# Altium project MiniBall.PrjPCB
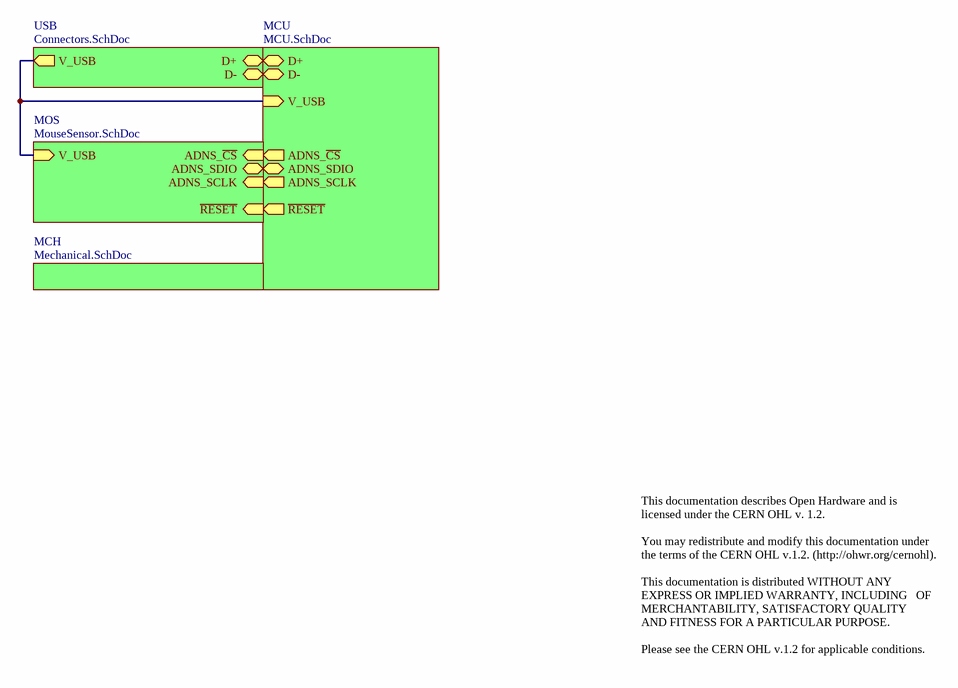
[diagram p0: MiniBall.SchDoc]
5 sheets, 44 parts. Net scope: hierarchical (ports join the sheet entries above them; power ports are global).
Board file: MiniBall.PcbDoc
Sheets:
  MiniBall.SchDoc
    USB = Connectors.SchDoc
    MCU = MCU.SchDoc
    MCH = Mechanical.SchDoc
    MOS = MouseSensor.SchDoc

## Sheet MiniBall.SchDoc
size Letter; CompanyName: Ploopy Corporation; Organization: Ploopy Corporation; Address1: 137-1140 Burnhamthorpe Road W; Address2: Mississauga; Address3: Ontario; Address4: Canada L5C 0A3; DocumentNumber: 1; Revision: R1.001; SheetNumber: 1; SheetTotal: 5

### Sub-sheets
MCH = Mechanical.SchDoc: no entries
MCU = MCU.SchDoc: D+ (bidir), D- (bidir), V_USB (in), ~{RESET} (out), ADNS_SDIO (bidir), ADNS_~{CS} (out), ADNS_SCLK (out)
MOS = MouseSensor.SchDoc: ~{RESET} (in), V_USB (in), ADNS_~{CS} (in), ADNS_SDIO (bidir), ADNS_SCLK (in)
USB = Connectors.SchDoc: D+ (bidir), V_USB (out), D- (bidir)

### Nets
~{RESET}: sheet MCU/~{RESET}, sheet MOS/~{RESET}
V_USB: sheet USB/V_USB, sheet MCU/V_USB, sheet MOS/V_USB
NetR6_2: sheet USB/D-, sheet MCU/D-
NetR7_2: sheet USB/D+, sheet MCU/D+
NetU1_12: sheet MCU/ADNS_SCLK, sheet MOS/ADNS_SCLK
NetU1_28: sheet MCU/ADNS_~{CS}, sheet MOS/ADNS_~{CS}
NetU1_31: sheet MCU/ADNS_SDIO, sheet MOS/ADNS_SDIO

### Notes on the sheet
- This documentation describes Open Hardware and is licensed under the CERN OHL v. 1.2.
  You may redistribute and modify this documentation under the terms of the CERN OHL v.1.2. (http://ohwr.org/cernohl).
  This documentation is distributed WITHOUT ANY EXPRESS OR IMPLIED WARRANTY, INCLUDING   OF MERCHANTABILITY, SATISFACTORY QUALITY   AND FITNESS FOR A PARTICULAR PURPOSE.
  Please see the CERN OHL v.1.2 for applicable conditions.

## Sheet Connectors.SchDoc
size Letter; CompanyName: Ploopy Corporation; Organization: Ploopy Corporation; Address1: 137-1140 Burnhamthorpe Road W; Address2: Mississauga; Address3: Ontario; Address4: Canada L5C 0A3; DocumentNumber: 2; Revision: R1.001; SheetNumber: 2; SheetTotal: 5
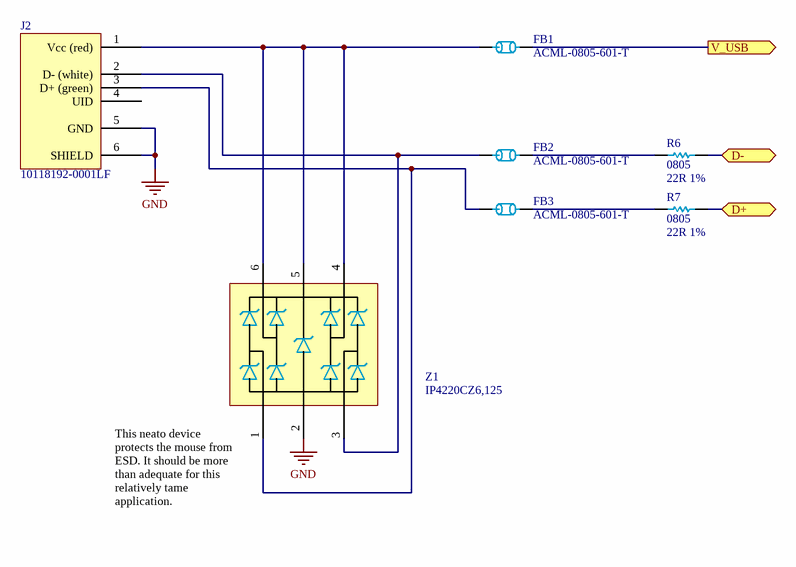
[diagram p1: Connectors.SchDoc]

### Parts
FB1  ACML-0805-601-T  [0805]
FB2  ACML-0805-601-T  [0805]
FB3  ACML-0805-601-T  [0805]
J2  10118192-0001LF  [10118192-0001LF]
R6  0805  value 22R 1%  [0805]
R7  0805  value 22R 1%  [0805]
Z1  IP4220CZ6,125  [PESD3V3S4UD - SOT95P275X110-6N]

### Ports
D+ (bidir), D- (bidir), V_USB (out)

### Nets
GND: J2.5(GND) J2.6(SHIELD) Z1.2
V_USB: FB1.2 ; port V_USB
NetFB1_1: FB1.1 J2.1(Vcc_(red)) Z1.4 Z1.5 Z1.6
NetFB2_1: FB2.1 J2.2(D-_(white)) Z1.3
NetFB2_2: FB2.2 R6.1
NetFB3_1: FB3.1 J2.3(D+_(green)) Z1.1
NetFB3_2: FB3.2 R7.1
NetR6_2: R6.2 ; port D-
NetR7_2: R7.2 ; port D+

Not connected (* = marked no-connect by the designer): J2 4(UID)

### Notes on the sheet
- (near Z1) This neato device protects the mouse from ESD. It should be more than adequate for this relatively tame application.

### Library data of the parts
FB1-FB3 = ACML-0805-601-T: FERRITE BEAD 600 OHM 0805 1LN; Value: Ferrite Bead 600R
J2 = 10118192-0001LF: CONN RCPT USB2.0 MICRO B SMD R/A
R6 R7 = Res 22R 1% 0805: Chip resistor
Z1 = IP4220CZ6,125: TVS DIODE 5.5V 6TSOP (Low capacitance, USB)

## Sheet MCU.SchDoc
size Legal; CompanyName: Ploopy Corporation; Organization: Ploopy Corporation; Address1: 137-1140 Burnhamthorpe Road W; Address2: Mississauga; Address3: Ontario; Address4: Canada L5C 0A3; DocumentNumber: 3; Revision: R1.001; SheetNumber: 3; SheetTotal: 5
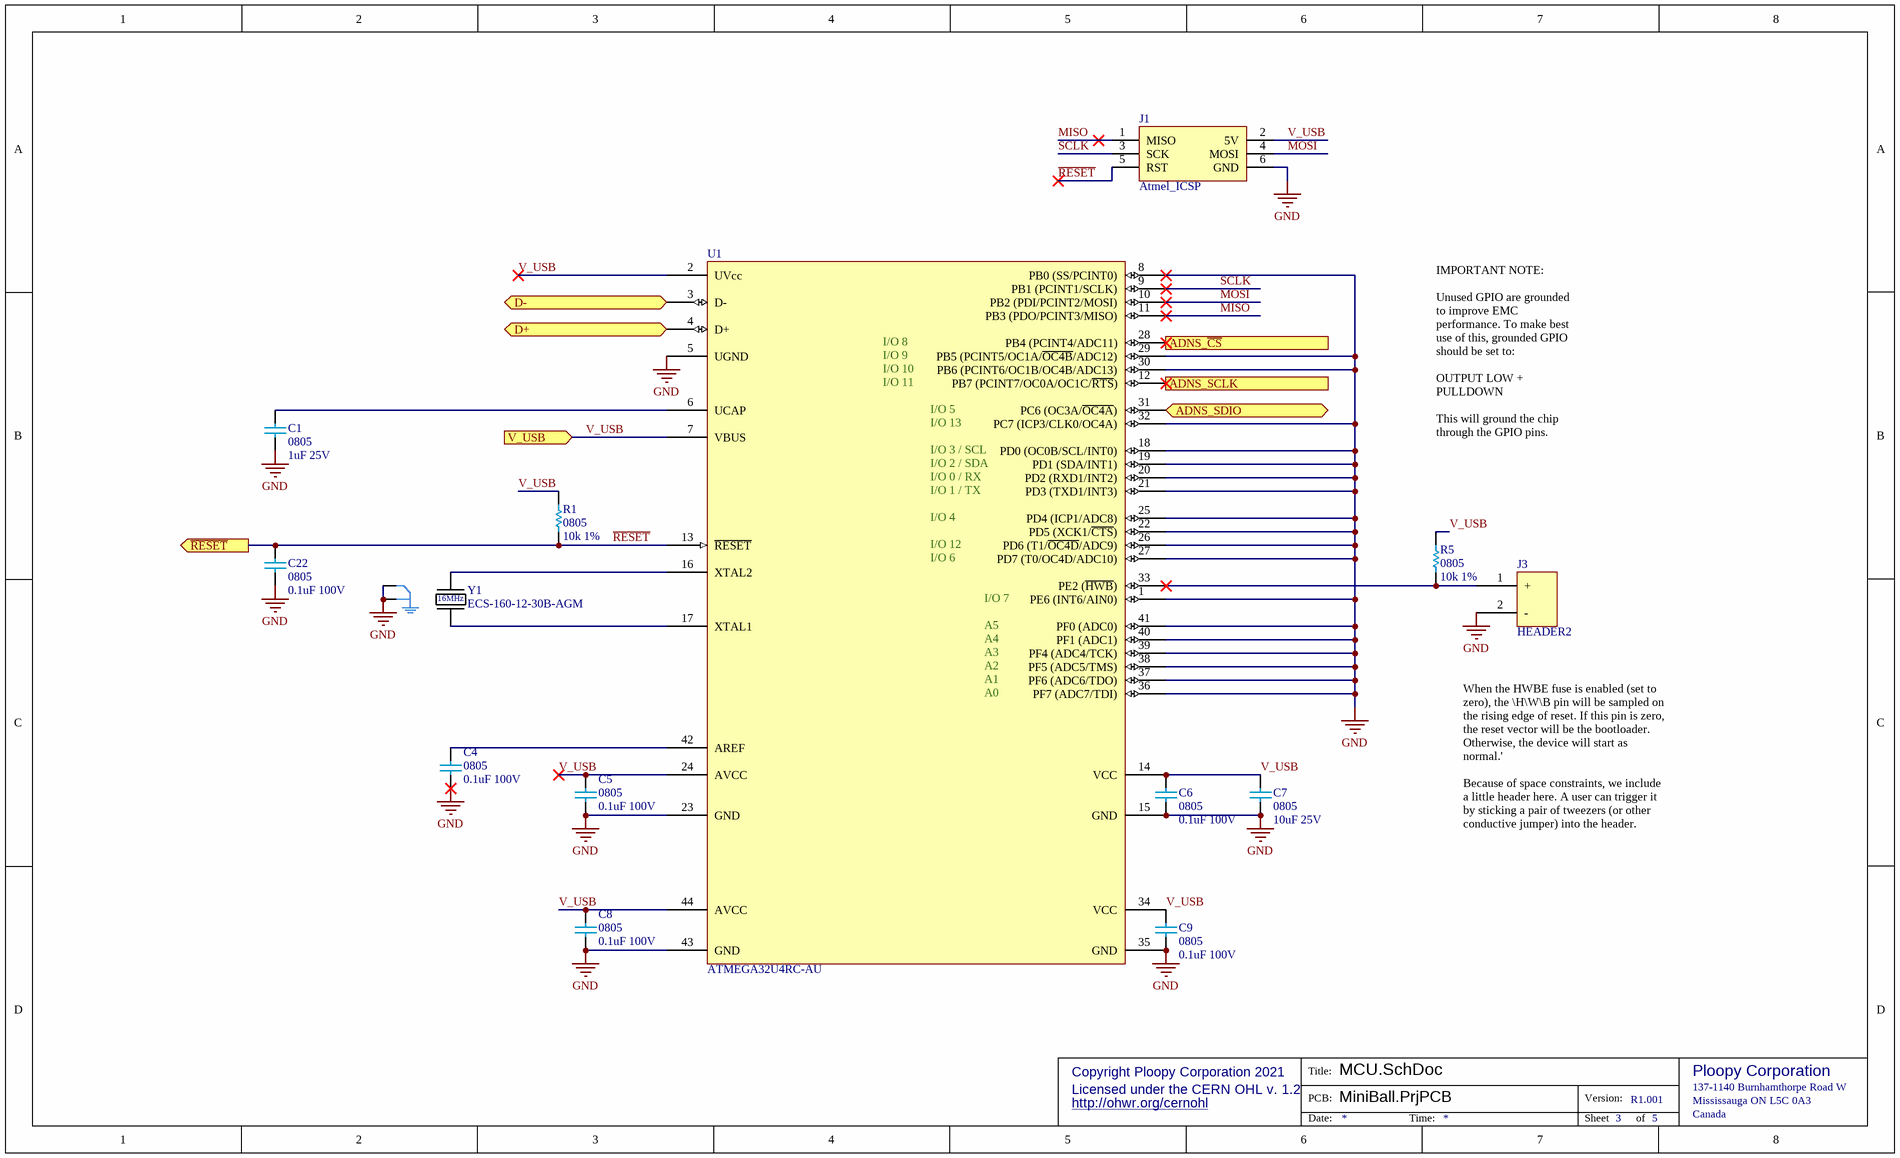
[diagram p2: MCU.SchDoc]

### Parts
C1  0805  value 1uF 25V  [0805 - TALL]
C4  0805  value 0.1uF 100V  [0805 - TALL]
C5  0805  value 0.1uF 100V  [0805 - TALL]
C6  0805  value 0.1uF 100V  [0805 - TALL]
C7  0805  value 10uF 25V  [0805 - TALL]
C8  0805  value 0.1uF 100V  [0805 - TALL]
C9  0805  value 0.1uF 100V  [0805 - TALL]
C22  0805  value 0.1uF 100V  [0805 - TALL]
J1  Atmel_ICSP  [6x2]
J3  HEADER2  [2x1]
R1  0805  value 10k 1%  [0805]
R5  0805  value 10k 1%  [0805]
U1  ATMEGA32U4RC-AU  [ATmega32U4 - TQFP80P1200X1200X120-44N]
Y1  ECS-160-12-30B-AGM  [LFXTAL055663BULK]

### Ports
ADNS_SCLK (out), ADNS_SDIO (bidir), ADNS_~{CS} (out), D+ (bidir), D- (bidir), V_USB (in), ~{RESET} (out)

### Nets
GND: C1.1 C4.1 C5.1 C6.1 C7.1 C8.1 C9.1 C22.1 J1.6(GND) J3.2(-) U1.1(PE6_(INT6/AIN0)) U1.5(UGND) U1.8(PB0_(SS/PCINT0)) U1.15(GND) U1.18(PD0_(OC0B/SCL/INT0)) U1.19(PD1_(SDA/INT1)) U1.20(PD2_(RXD1/INT2)) U1.21(PD3_(TXD1/INT3)) U1.22(PD5_(XCK1/~{CTS})) U1.23(GND) U1.25(PD4_(ICP1/ADC8)) U1.26(PD6_(T1/~{OC4D}/ADC9)) U1.27(PD7_(T0/OC4D/ADC10)) U1.29(PB5_(PCINT5/OC1A/~{OC4B}/ADC12)) U1.30(PB6_(PCINT6/OC1B/OC4B/ADC13)) U1.32(PC7_(ICP3/CLK0/OC4A)) U1.35(GND) U1.36(PF7_(ADC7/TDI)) U1.37(PF6_(ADC6/TDO)) U1.38(PF5_(ADC5/TMS)) U1.39(PF4_(ADC4/TCK)) U1.40(PF1_(ADC1)) U1.41(PF0_(ADC0)) U1.43(GND) Y1.2 Y1.4
MISO: J1.1(MISO) U1.11(PB3_(PDO/PCINT3/MISO))
MOSI: J1.4(MOSI) U1.10(PB2_(PDI/PCINT2/MOSI))
~{RESET}: C22.2 J1.5(RST) R1.1 U1.13(~{RESET}) ; port ~{RESET}
SCLK: J1.3(SCK) U1.9(PB1_(PCINT1/SCLK))
V_USB: C5.2 C6.2 C7.2 C8.2 C9.2 J1.2(5V) R1.2 R5.2 U1.2(UVcc) U1.7(VBUS) U1.14(VCC) U1.24(AVCC) U1.34(VCC) U1.44(AVCC) ; port V_USB
NetC1_2: C1.2 U1.6(UCAP)
NetC4_2: C4.2 U1.42(AREF)
NetJ3_1: J3.1(+) R5.1 U1.33(PE2_(~{HWB}))
NetR6_2: U1.3(D-) ; port D-
NetR7_2: U1.4(D+) ; port D+
NetU1_12: U1.12(PB7_(PCINT7/OC0A/OC1C/~{RTS})) ; port ADNS_SCLK
NetU1_16: U1.16(XTAL2) Y1.1
NetU1_17: U1.17(XTAL1) Y1.3
NetU1_28: U1.28(PB4_(PCINT4/ADC11)) ; port ADNS_~{CS}
NetU1_31: U1.31(PC6_(OC3A/~{OC4A})) ; port ADNS_SDIO

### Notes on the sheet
- IMPORTANT NOTE:
  Unused GPIO are grounded to improve EMC performance. To make best use of this, grounded GPIO should be set to:
  OUTPUT LOW + PULLDOWN
  This will ground the chip through the GPIO pins.
- When the HWBE fuse is enabled (set to zero), the \H\W\B pin will be sampled on the rising edge of reset. If this pin is zero, the reset vector will be the bootloader. Otherwise, the device will start as normal.'
  Because of space constraints, we include a little header here. A user can trigger it by sticking a pair of tweezers (or other conductive jumper) into the header.

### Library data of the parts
C1 = Cap 1uF 25V: 0805, X5R or better
C4-C6 C8 C9 C22 = Cap 0.1uF 100V: 0805, X5R or better
C7 = Cap 10uF 25V: 0805, X5R or better
J1 = Atmel_ICSP: 6-pin 0.100" ICSP header
J3 = HEADER2: 2-pin 0.100" header
R1 R5 = Res 10k 1% 0805: Chip resistor
U1 = ATMEGA32U4RC-AU: IC MCU 8BIT 32KB FLASH 44TQFP; PNP-Nzl: 6; PNP-dx: 0; PNP-X: 12; PNP-A: 270; PNP-Pt: 1; PNP-W: 0.1; PNP-Thk: 1.6; PNP-Lv: 126; PNP-TS: 70; PNP-Level: 1.2; PNP-Type: QFP; PNP-FeedType: Tray; PNP-PlacePriority: 3
Y1 = ECS-160-12-30B-AGM: 16MHz Crystal 12pF 100 Ohms 4-SMD, No Lead

## Sheet Mechanical.SchDoc
size Letter; CompanyName: Ploopy Corporation; Organization: Ploopy Corporation; Address1: 137-1140 Burnhamthorpe Road W; Address2: Mississauga; Address3: Ontario; Address4: Canada L5C 0A3; DocumentNumber: 4; Revision: R1.001; SheetNumber: 4; SheetTotal: 5
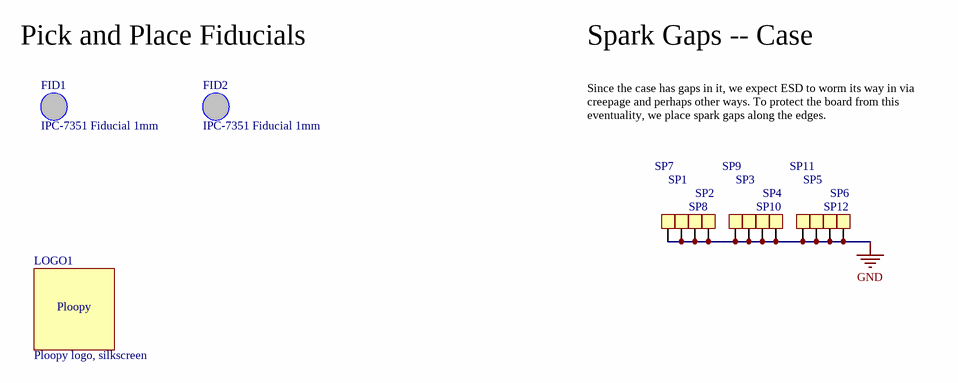
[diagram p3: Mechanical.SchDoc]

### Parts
FID1  IPC-7351 Fiducial 1mm  [FIDUCIAL_1.5]
FID2  IPC-7351 Fiducial 1mm  [FIDUCIAL_1.5]
LOGO1  Ploopy logo, silkscreen  [PloopyLogo]  (no BOM)
SP1  Spark Gap  [SparkGap]  (value not drawn)  (no BOM)
SP2  Spark Gap  [SparkGap]  (value not drawn)  (no BOM)
SP3  Spark Gap  [SparkGap]  (value not drawn)  (no BOM)
SP4  Spark Gap  [SparkGap]  (value not drawn)  (no BOM)
SP5  Spark Gap  [SparkGap]  (value not drawn)  (no BOM)
SP6  Spark Gap  [SparkGap]  (value not drawn)  (no BOM)
SP7  Spark Gap  [SparkGap]  (value not drawn)  (no BOM)
SP8  Spark Gap  [SparkGap]  (value not drawn)  (no BOM)
SP9  Spark Gap  [SparkGap]  (value not drawn)  (no BOM)
SP10  Spark Gap  [SparkGap]  (value not drawn)  (no BOM)
SP11  Spark Gap  [SparkGap]  (value not drawn)  (no BOM)
SP12  Spark Gap  [SparkGap]  (value not drawn)  (no BOM)

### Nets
GND: SP1.1 SP2.1 SP3.1 SP4.1 SP5.1 SP6.1 SP7.1 SP8.1 SP9.1 SP10.1 SP11.1 SP12.1

Not connected (* = marked no-connect by the designer): FID1 1; FID2 1

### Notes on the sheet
- Pick and Place Fiducials
- Spark Gaps -- Case
- Since the case has gaps in it, we expect ESD to worm its way in via creepage and perhaps other ways. To protect the board from this eventuality, we place spark gaps along the edges.

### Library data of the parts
FID1 FID2 = FIDUCIAL_1.5: PNP-Nzl: 2; PNP-dx: 0; PNP-X: 4; PNP-A: 1; PNP-Thk: 1.02; PNP-TS: 70; PNP-Type: MARK1
LOGO1 = PloopyLogo: PNP-Nzl: 2; PNP-dx: 0; PNP-X: 1; PNP-TS: 70; PNP-Type: CHI; PNP-FeedType: Tape; PNP-TapeWidth: 8
SP1-SP12 = Spark Gap: Open square pad for spark gapping; PNP-Nzl: 2; PNP-dx: 0; PNP-X: 1; PNP-TS: 70; PNP-Type: CHI; PNP-FeedType: Tape; PNP-TapeWidth: 8

## Sheet MouseSensor.SchDoc
size Letter; CompanyName: Ploopy Corporation; Organization: Ploopy Corporation; Address1: 137-1140 Burnhamthorpe Road W; Address2: Mississauga; Address3: Ontario; Address4: Canada L5C 0A3; DocumentNumber: 5; Revision: R1.001; SheetNumber: 5; SheetTotal: 5
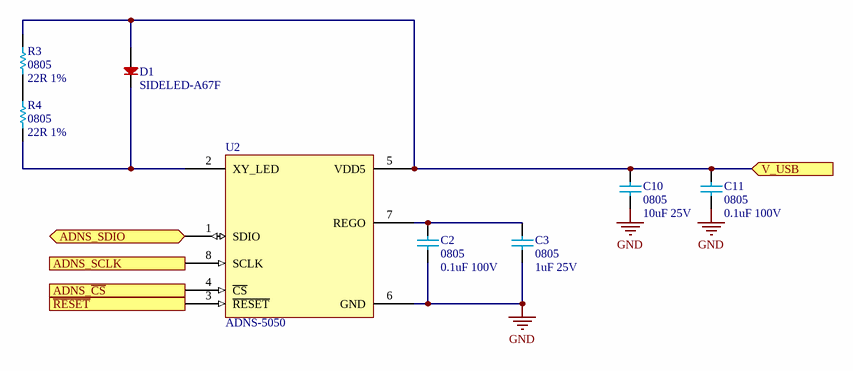
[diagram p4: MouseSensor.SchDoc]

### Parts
C2  0805  value 0.1uF 100V  [0805 - TALL]
C3  0805  value 1uF 25V  [0805 - TALL]
C10  0805  value 10uF 25V  [0805 - TALL]
C11  0805  value 0.1uF 100V  [0805 - TALL]
D1  SIDELED-A67F  [SIDELED-A67F]
R3  0805  value 22R 1%  [0805]
R4  0805  value 22R 1%  [0805]
U2  ADNS-5050  [ADNS-5050]

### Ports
ADNS_SCLK (in), ADNS_SDIO (bidir), ADNS_~{CS} (in), V_USB (in), ~{RESET} (in)

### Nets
GND: C2.1 C3.1 C10.1 C11.1 U2.6(GND)
~{RESET}: U2.3(~{RESET}) ; port ~{RESET}
V_USB: C10.2 C11.2 D1.A R3.2 U2.5(VDD5) ; port V_USB
NetC2_2: C2.2 C3.2 U2.7(REGO)
NetD1_C: D1.C R4.1 U2.2(XY_LED)
NetR3_1: R3.1 R4.2
NetU1_12: U2.8(SCLK) ; port ADNS_SCLK
NetU1_28: U2.4(~{CS}) ; port ADNS_~{CS}
NetU1_31: U2.1(SDIO) ; port ADNS_SDIO

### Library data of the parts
C2 C11 = Cap 0.1uF 100V: 0805, X5R or better
C3 = Cap 1uF 25V: 0805, X5R or better
C10 = Cap 10uF 25V: 0805, X5R or better
D1 = SIDELED-A67F: Red/Orange/Yellow Side-facing SMT LEDs, high brightness (~2lm)
R3 R4 = Res 22R 1% 0805: Chip resistor
U2 = ADNS-5050: Optical Mouse Navigation Sensor

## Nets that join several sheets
GND: Connectors (J2.5 J2.6 Z1.2), MCU (36 pins), Mechanical (12 pins), MouseSensor (5 pins)
NetR6_2: Connectors (R6.2), MCU (U1.3)
NetR7_2: Connectors (R7.2), MCU (U1.4)
NetU1_12: MCU (U1.12), MouseSensor (U2.8)
NetU1_28: MCU (U1.28), MouseSensor (U2.4)
NetU1_31: MCU (U1.31), MouseSensor (U2.1)
~{RESET}: MCU (C22.2 J1.5 R1.1 U1.13), MouseSensor (U2.3)
V_USB: Connectors (FB1.2), MCU (14 pins), MouseSensor (5 pins)

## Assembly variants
BoM: not fitted LED.C.21 LED.C.24 LED.C.26 LED.C.28 LED.D.2 LED.D.4 LED.D.6 LED.D.8 LED.R.17 LED.R.19 MCU.C.2 MCU.C.3 MCU.J.1 MCU.J.3 REG.C.13 REG.C.15 REG.C.17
